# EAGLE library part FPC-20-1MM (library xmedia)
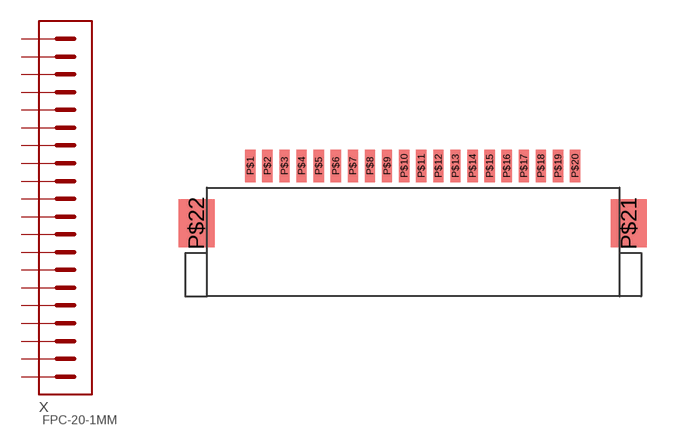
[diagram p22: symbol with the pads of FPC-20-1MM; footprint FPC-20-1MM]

Designator prefix X

## FPC-20-1MM  [FPC-20-1MM]
P$1  P$1
P$2  P$2
P$3  P$3
P$4  P$4
P$5  P$5
P$6  P$6
P$7  P$7
P$8  P$8
P$9  P$9
P$10  P$10
P$11  P$11
P$12  P$12
P$13  P$13
P$14  P$14
P$15  P$15
P$16  P$16
P$17  P$17
P$18  P$18
P$19  P$19
P$20  P$20

## Footprint FPC-20-1MM (pad centres in mm)
smd 0.6 x 1.9: P$1 0,0; P$2 1,0; P$3 2,0; P$4 3,0; P$5 4,0; P$6 5,0; P$7 6,0; P$8 7,0; P$9 8,0; P$10 9,0; P$11 10,0; P$12 11,0; P$13 12,0; P$14 13,0; P$15 14,0; P$16 15,0; P$17 16,0; P$18 17,0; P$19 18,0; P$20 19,0
smd 2.1 x 2.8: P$21 22.15,-3.35; P$22 -3.15,-3.35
